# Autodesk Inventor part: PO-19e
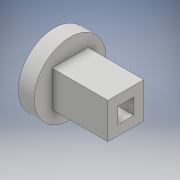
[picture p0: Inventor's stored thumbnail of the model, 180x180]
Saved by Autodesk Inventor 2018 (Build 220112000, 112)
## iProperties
Created: 2020-01
Part Number: PO-19e
Material: Générique
Document SubType Name: Modeling
Designer: TJ
Density: 1 g/cm^3
Appearance: Par défaut
Author: TJ
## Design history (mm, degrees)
sketch "Esquisse1"
  geometry: C1 r 18 at (0, 0); 1 further point
  constraints: 1 centre point, 1 coincident
  dimensions: "d0" = 36 diameter of C1
extrude "Extrusion1" new body sketch "Esquisse1" distance "d1" = 8; taper "d2" = 0 deg
sketch "Esquisse2"
  geometry: L1 (-9, 9)-(9, 9); L2 (9, 9)-(9, -9); L3 (9, -9)-(-9, -9); L4 (-9, -9)-(-9, 9); L5 (-9, 9)-(9, -9); L6 (9, 9)-(-9, -9); 1 further point
  constraints: 12 end point, 2 midpoint, 2 parallel, 1 horizontal, 1 perpendicular
  dimensions: "d3" = 18 distance of L1.start L1.end; "d4" = 18 distance of L3.end L1.start (= d3)
extrude "Extrusion2" join sketch "Esquisse2" distance "d5" = 28; taper "d6" = 0 deg
sketch "Esquisse3"
  geometry: L1 (-4, 4)-(4, 4); L2 (4, 4)-(4, -4); L3 (4, -4)-(-4, -4); L4 (-4, -4)-(-4, 4); L5 (-9, -9)-(9, -9) reference; 1 further point
  constraints: 8 end point, 2 perpendicular, 1 parallel
  dimensions: "d7" = 0 deg angle of L5 L3; "d8" = 8 distance of L3.end L1.start; "d9" = 8 distance of L1.start L1.end; "d10" = 4 horizontal distance of L3.end point (0, 0) (= 0.5 x d9); "d15" = 4 distance from line of point (0, 0) L1
extrude "Extrusion3" cut sketch "Esquisse3" extent not by distance; stored distance "d13" = 28; taper "d14" = 0 deg
node "Solide1"
